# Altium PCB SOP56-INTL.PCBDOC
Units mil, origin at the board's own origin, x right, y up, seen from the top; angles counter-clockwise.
Board outline 1247.64 x 3931.89 mil, 2 copper layers (Top Layer, Bottom Layer); 6 components, 340 nets, 107 pads, 37 vias.
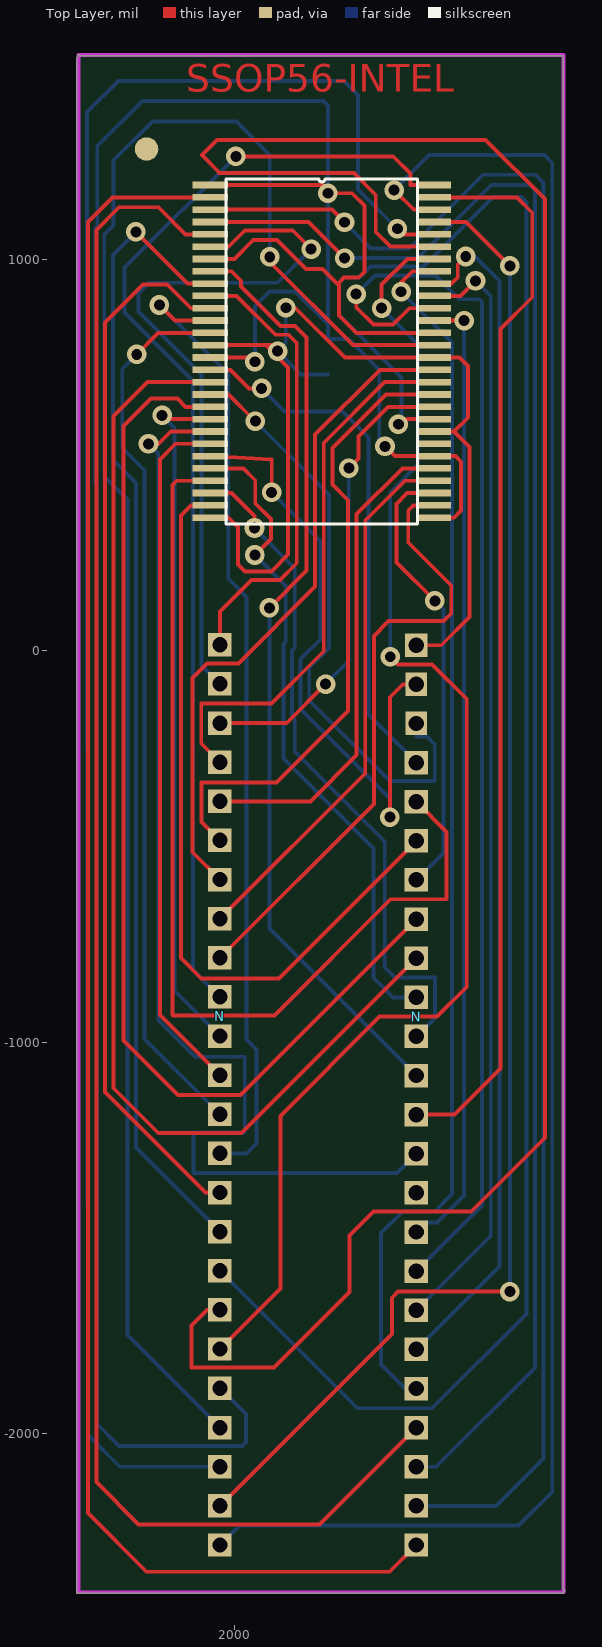
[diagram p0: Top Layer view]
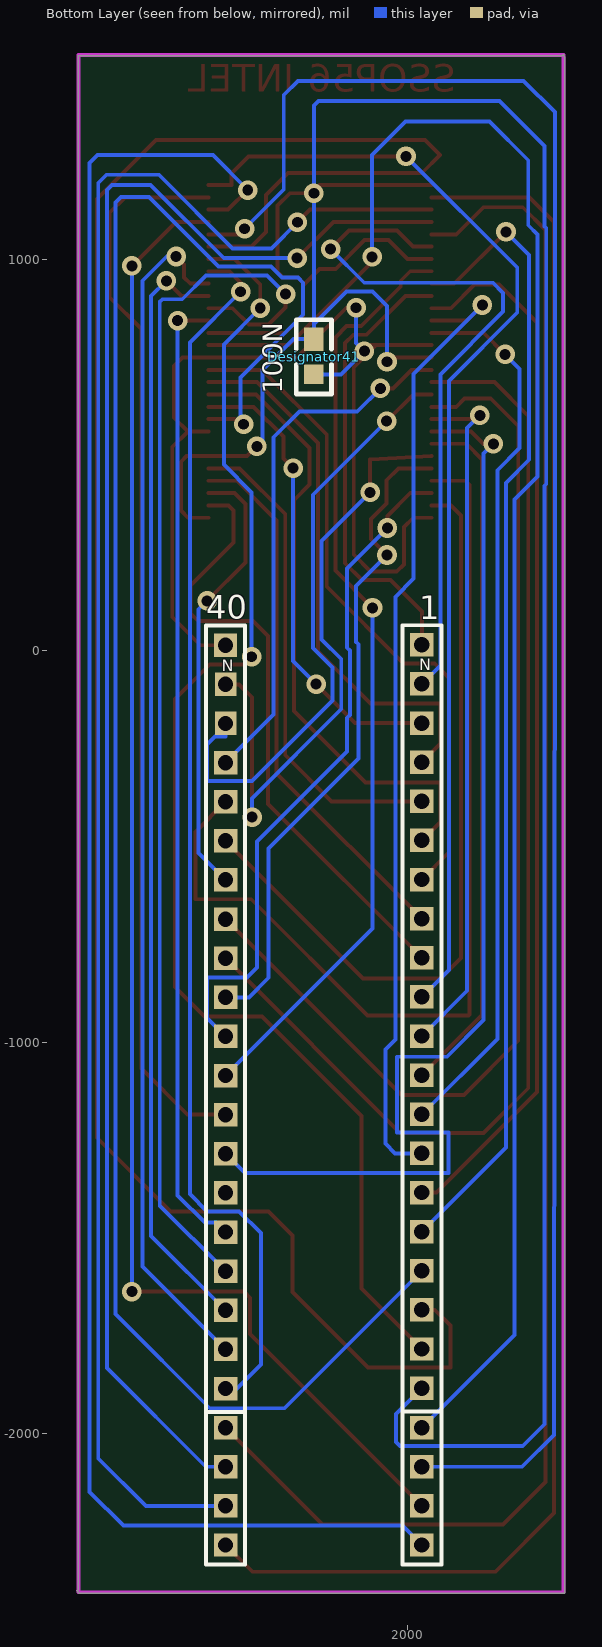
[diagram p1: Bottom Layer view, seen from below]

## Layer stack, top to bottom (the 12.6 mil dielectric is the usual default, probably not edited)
Top Layer: signal copper 1.4
Dielectric: dielectric 12.6, FR-4, Dk 4.8
Bottom Layer: signal copper 1.4

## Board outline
1599.21,1523.62 1601.18,1521.65 2840.94,1521.65 2840.94,-2398.43 2844.88,-2402.36 2838.98,-2408.27 1597.24,-2408.27 1597.24,1517.72 1603.15,1523.62

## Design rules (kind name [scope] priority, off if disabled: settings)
Clearance [All] p1: gap=12
ComponentClearance [All] p1 off: gap=10 collisioncheckmode=3 verticalgap=10 showdistances=FALSE
FabricationTestPointUsage TestPointUsage [All] p1: valid=0 allowmultiple=FALSE
FabricationTestpoint Testpoint [All] p1: side=3 testpointundercomponent=TRUE minsize=40 maxsize=100 preferedsize=60 minholesize=0 maxholesize=40 preferedholesize=32 testpointgrid=1 allowsidetop=TRUE allowsidebottom=TRUE usegrid=TRUE gridtolerance=0.01
HoleSize [All] p1: absolutevalues=TRUE maxlimit=1000 minlimit=1 maxpercent=80.000 minpercent=20.000
PolygonConnect [All] p1: connectstyle=Relief reliefconductorwidth=10 reliefentries=4 polygonreliefangle="90 Angle"
RoutingVias [All] p1: holewidth=28 width=50 viastyle="Through Hole" minholewidth=28 minwidth=50 maxholewidth=28 maxwidth=50
ShortCircuit [All] p1 off: allowed=FALSE
SilkscreenOverComponentPads [All] p1: minsilkscreentomaskgap=10
SolderMaskExpansion [All] p1: expansion=4
Width [All] p1: maxlimit=1000 minlimit=10 preferedwidth=10
22 further rules are at their usual default settings.

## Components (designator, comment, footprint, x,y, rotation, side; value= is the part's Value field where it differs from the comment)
Designator41 "100N" 0805 2239,797 r270 bottom
N "40" SIP20A#1 2464.92,14.69 r270 top
N "1" SIP20A#2 1962.92,15.68 r270 top
? "Comment" sip4#1 2464.92,-1985.32 r270 bottom
? "Comment" sip4#2 1962.92,-1985.32 r270 bottom
? "Comment" SOP56 1938,1191 r0 top

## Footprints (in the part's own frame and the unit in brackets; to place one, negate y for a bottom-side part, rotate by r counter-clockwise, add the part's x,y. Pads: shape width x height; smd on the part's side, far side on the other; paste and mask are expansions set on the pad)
0805 [mil]
  rect 60x50 smd: 1(0,0)
  rect 50x50 smd: 2(90,0)
  silkscreen extent -50,-45 140,45
sip4#1 [mil]
  rect 60x60 hole 39.37 mask+4: 25(300,0) 26(200,0) 27(100,0) 28(0,0)
  silkscreen extent -50,-50 350,50
sip4#2 [mil]
  rect 60x60 hole 39.37 mask+4: 21(0,0) 22(100,0) 23(200,0) 24(300,0)
  silkscreen extent -50,-50 350,50
SIP20A#1 [mil]
  rect 60x60 hole 39.37: 29(1900,0) 30(1800,0) 31(1700,0) 32(1600,0) 33(1500,0) 34(1400,0) 35(1300,0) 36(1200,0) 37(1100,0) 38(1000,0) 39(900,0) 40(800,0) 41(700,0) 42(600,0) 43(500,0) 44(400,0) 45(300,0)
  rect 60x55 hole 39.37: 46(200,0) 47(100,0)
  rect 60x58 hole 39.37: 48(0,0)
SIP20A#2 [mil]
  rect 60x60 hole 39.37: 1(0,0) 2(100,0) 3(200,0) 4(300,0) 5(400,0) 6(500,0) 7(600,0) 8(700,0) 9(800,0) 10(900,0) 11(1000,0) 12(1100,0) 13(1200,0) 14(1300,0) 15(1400,0) 16(1500,0) 17(1600,0) 18(1700,0) 19(1800,0) 20(1900,0)
SOP56 [mil]
  rect 90x17 smd: 1(0,0) 2(0,-31.5) 3(0,-62.99) 4(0,-94.49) 5(0,-125.98) 6(0,-157.48) 7(0,-188.98) 8(0,-220.47) 9(0,-251.97) 10(0,-283.46) 11(0,-314.96) 12(0,-346.46) 13(0,-377.95) 14(0,-409.45) 15(0,-440.95) 16(0,-472.44) 17(0,-503.94) 18(0,-535.43) 19(0,-566.93) 20(0,-598.43) 21(0,-629.92) 22(0,-661.42) 23(0,-692.91) 24(0,-724.41) 25(0,-755.91) 26(0,-787.4) 27(0,-818.9) 28(0,-850.39) 29(570.87,-850.39) 30(570.87,-818.9) 31(570.87,-787.4) 32(570.87,-755.91) 33(570.87,-724.41) 34(570.87,-692.91) 35(570.87,-661.42) 36(570.87,-629.92) 37(570.87,-598.43) 38(570.87,-566.93) 39(570.87,-535.43) 40(570.87,-503.94) 41(570.87,-472.44) 42(570.87,-440.95) 43(570.87,-409.45) 44(570.87,-377.95) 45(570.87,-346.46) 46(570.87,-314.96) 47(570.87,-283.46) 48(570.87,-251.97) 49(570.87,-220.47) 50(570.87,-188.98) 51(570.87,-157.48) 52(570.87,-125.98) 53(570.87,-94.49) 54(570.87,-62.99) 55(570.87,-31.5) 56(570.87,0)
  silkscreen extent 41,-866 530,16

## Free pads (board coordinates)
  round 60 smd: 0(1775.2,1283.07)

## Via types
v1: diameter 50, hole 28, Top Layer to Bottom Layer, 37 vias

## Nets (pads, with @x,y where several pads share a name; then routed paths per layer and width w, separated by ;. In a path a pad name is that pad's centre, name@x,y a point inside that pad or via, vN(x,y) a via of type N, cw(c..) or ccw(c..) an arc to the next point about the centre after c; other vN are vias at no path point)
a0: ?.37 N.17 | length 4962.1
  Top Layer w10: v1@2427.21,578.24 2441.54,592.57 ?.37
  Bottom Layer w10: N.17 2314.37,-1935.76 2505.21,-1935.76 2746.21,-1694.76 2746.21,1146.24 2732.21,1160.24 2660.9,1160.24 2482.9,982.24 2348.21,982.24 2320.21,954.24 2280.21,954.24 2267.21,941.24 2267.21,859.43 2427.21,699.43 v1@2427.21,578.24
  other v1: 2418.9,579.53
a1: ?.51 N.18 | length 5529.3
  Top Layer w10: 1959.84,1221.24 2305.21,1221.24 2361.21,1165.24 2361.21,1071.24 2398.93,1033.52 ?.51 ; 1962.2,1222.44 1916.73,1267.91 1955.06,1306.24 2642.21,1306.24 2793.7,1154.75 2793.7,-1244.27 2605.21,-1432.76 2355.21,-1432.76 2294.21,-1493.76 2294.21,-1638.76 2101.21,-1831.76 1890.16,-1831.76 1890.16,-1724.37 1930.21,-1684.31 N.18
a2: ?.50 N.19 | length 3427.7
  Top Layer w10: N.19 2117.21,-1630.03 2117.21,-1188.76 2371.21,-934.76 2518.21,-934.76 2593.7,-859.27 2593.7,-123.25 2505.21,-34.76 2418.21,-34.76 v1(2398.21,-14.76) ; v1(2376.21,876.24) 2376.21,936.24 2441.99,1002.02 ?.50
  Bottom Layer w10: v1(2376.21,876.24) 2469.21,783.24 2469.21,476.24 2398.21,405.24 v1(2398.21,-14.76)
a3: ?.49 N.29 | length 3152.8
  Top Layer w10: v1(2426.21,918.24) 2426.21,941.53 2455.21,970.53 ?.49
  Bottom Layer w10: v1(2426.21,918.24) 2556.21,788.24 2556.21,-1388.03 2511.92,-1432.31 2430.21,-1432.31 2374.8,-1487.72 2374.8,-1824.41 2435.71,-1885.31 N.29
a4: ?.48 N.30 | length 3061.6
  Top Layer w10: ?.48 2555.21,939.03 2570.87,954.69 2570.87,987.9 v1(2591.21,1008.24)
  Bottom Layer w10: N.30 2677.21,-1573.03 2677.21,946.24 2615.21,1008.24 v1(2591.21,1008.24)
a5: ?.47 N.31 | length 2849.9
  Top Layer w10: ?.47 2577.5,907.54 v1(2616.21,946.24)
  Bottom Layer w10: N.31 2655.21,-1495.03 2655.21,907.24 v1(2616.21,946.24)
a6: ?.46 N.32 | length 3184.5
  Top Layer w10: v1(2311.21,912.24) 2311.21,878.24 2355.21,834.24 2405.21,834.24 2447.01,876.04 ?.46
  Bottom Layer w10: v1(2311.21,912.24) 2359.21,960.24 2514.37,960.24 2575.68,898.93 2626.52,898.93 2633.21,892.24 2633.21,-1417.03 N.32
a7: ?.45 N.33 | length 2475.5
  Top Layer w10: ?.45 v1(2587.21,844.54)
  Bottom Layer w10: N.33 2489.33,-1460.91 2517.71,-1460.91 2587.21,-1391.41 v1(2587.21,844.54)
a8: ?.21@1962.92,-1985.31 ?.43 | length 4627.7
  Top Layer w10: v1(2090.21,1007.24) 2090.21,994.55 2303.21,781.55 ?.43
  Bottom Layer w10: ?.21@1962.92,-1985.31 1726.21,-1748.6 1726.21,387.24 1667.18,446.27 1667.18,1064.14 1691.21,1088.17 1691.21,1254.24 1790.21,1353.24 2005.01,1353.24 2090.21,1268.04 v1(2090.21,1007.24)
a9: ?.22@1962.92,-2085.31 ?.52 | length 4975.5
  Top Layer w10: v1(2416.21,1079.24) 2430.44,1065.02 ?.52
  Bottom Layer w10: ?.22@1962.92,-2085.31 1706.77,-2085.31 1625.21,-2003.76 1623.18,329.27 1623.18,1377.22 1703.21,1457.24 2280.21,1457.24 2316.21,1421.24 2316.21,1179.24 v1(2416.21,1079.24)
a10: ?.23@1962.92,-2185.31 ?.53 | length 3886.3
  Top Layer w10: ?.23@1962.92,-2185.31 2402.21,-1746.03 2402.21,-1653.26 2417.71,-1637.76 v1(2704.21,-1637.76) ; ?.53 2591.94,1096.51 v1(2704.21,984.24)
  Bottom Layer w10: v1(2704.21,-1637.76) v1(2704.21,984.24)
a11: ?.24@1962.92,-2285.31 ?.54 | length 4873.3
  Top Layer w10: v1(2408.21,1178.01) 2458.21,1128.01 ?.54
  Bottom Layer w10: ?.24@1962.92,-2285.31 2012.48,-2235.76 2726.21,-2235.76 2812.21,-2149.76 2812.21,1247.74 2792.71,1267.24 2497.45,1267.24 v1(2408.21,1178.01)
a12: ?.2 ?.25@2464.92,-2285.31 | length 4569.2
  Top Layer w10: ?.2 1688.47,1159.5 1625.21,1096.24 1625.21,-2203.76 1775.21,-2353.76 2396.48,-2353.76 ?.25@2464.92,-2285.31
a13: ?.3 ?.26@2464.92,-2185.31 | length 4615.4
  Top Layer w10: ?.3 2249.09,1128.01 v1(2281.21,1095.89)
  Bottom Layer w10: v1(2281.21,1095.89) 2347.97,1029.13 2446.85,1029.13 2634.96,1217.24 2769.21,1217.24 2790.21,1196.24 2790.21,-2063.76 2668.65,-2185.31 ?.26@2464.92,-2185.31
a14: ?.4 ?.27@2464.92,-2085.31 | length 4370.1
  Top Layer w10: ?.4 2189.44,1096.51 v1(2281.71,1004.24)
  Bottom Layer w10: v1(2281.71,1004.24) 2469.44,1004.24 2656.44,1191.24 2755.21,1191.24 2768.21,1178.24 2768.21,-1832.58 2515.47,-2085.31 ?.27@2464.92,-2085.31
a15: ?.5 ?.28@2464.92,-1985.31 | length 4509.4
  Top Layer w10: ?.5 1875.21,1065.02 1805.98,1134.24 1705.21,1134.24 1647.21,1076.24 1647.21,-2124.76 1755.21,-2232.76 2217.48,-2232.76 ?.28@2464.92,-1985.31
a16: ?.13 N.13 | length 2271.8
  Top Layer w10: v1(1750.21,758.24) 1805.01,813.05 ?.13
  Bottom Layer w10: v1(1750.21,758.24) 1713.21,721.24 1713.21,518.95 1770.21,461.95 1770.21,-991.6 N.13
a17: ?.12 N.14 | length 2496.4
  Top Layer w10: v1(1808.21,884.24) 1847.91,844.54 ?.12
  Bottom Layer w10: v1(1808.21,884.24) 1984.21,708.24 1984.21,184.69 2030.71,138.19 2030.71,-993.31 2056.3,-1018.9 2056.3,-1259.45 2031.43,-1284.31 N.14
a18: ?.11 N.15 | length 2700.9
  Top Layer w10: ?.11 1888.41,876.04 1828.21,936.24 1766.21,936.24 1669.21,839.24 1669.21,-1127.76 1925.77,-1384.31 N.15
a19: ?.10 N.1 | length 1166.4
  Top Layer w10: ?.10 2005.21,907.54 2104.5,808.24 2137.97,808.24 2159.21,787.01 2159.21,224.24 2116.21,181.24 2043.42,181.24 1962.92,100.75 N.1
a20: ?.9 N.16 | length 2937.9
  Top Layer w10: v1(1748.1,1071.14) 1880.21,939.03 ?.9
  Bottom Layer w10: v1(1748.1,1071.14) 1689.18,1012.22 1689.18,488.8 1748.21,429.77 1748.21,-1269.6 N.16
a21: ?.8 N.37 | length 2406.7
  Top Layer w10: ?.8 1992.84,970.53 2017.12,946.24 2017.12,931.24 2118.11,830.24 2155.21,830.24 2184.21,801.24 2184.21,205.24 v1(2089.21,110.24)
  Bottom Layer w10: v1(2089.21,110.24) 2089.21,-709.6 N.37
a22: ?.6 N.2 | length 1867.5
  Top Layer w10: ?.6 1985.49,1033.52 2026.21,1074.24 2149.06,1074.24 v1(2196.21,1027.1)
  Bottom Layer w10: N.2 1915.92,-37.31 1915.92,706.53 1755.21,867.24 1755.21,915.24 1781.21,941.24 2110.36,941.24 v1(2196.21,1027.1)
a23: N.34
a24: ?.23@1938,498.09 N.47 | length 1625.8
  Top Layer w10: ?.23@1938,498.09 2095.21,489.24 v1(2095.21,405.24) ; v1(2397.21,-424.76) 2397.21,-118.31 2430.21,-85.31 N.47
  Bottom Layer w10: v1(2095.21,405.24) 2219.21,281.24 2219.21,29.24 2169.21,-20.76 2169.21,-148.76 2397.21,-376.76 v1(2397.21,-424.76)
a25: 
a26: 
b1: 
b2: 
b3: 
b4: 
b5: 
b6: 
b7: 
b8: 
b9: 
b10: 
b11: 
b12: 
b13: 
b14: 
b16: 
b17: 
b18: 
b19: 
b20: 
b21: 
b22: 
byte: 
ce: 
CE1: 
CS: 
D0: ?.38 N.3 | length 1202.4
  Top Layer w10: N.3 2133.65,-184.31 v1(2233.21,-84.76) ; v1(2292.21,467.24) 2317.21,492.24 2317.21,548.31 2392.97,624.07 ?.38
  Bottom Layer w10: v1(2233.21,-84.76) 2292.21,-25.76 v1(2292.21,467.24)
D1: ?.40 N.4 | length 1415
  Top Layer w10: N.4 1915.21,-236.6 1915.21,-134.76 2094.21,-134.76 2228.21,-0.76 2228.21,531.24 2384.03,687.06 ?.40
D2: ?.33 N.5 | length 1259.2
  Top Layer w10: N.5 2194.21,-384.31 2312.21,-266.31 2312.21,349.59 2429.21,466.59 ?.33
D3: ?.31 N.42 | length 1146
  Top Layer w10: ?.31 2441.56,403.6 2413.91,375.94 2413.91,226.55 v1(2512.21,128.24)
  Bottom Layer w10: N.42 2533.92,-516.31 2533.92,106.53 v1(2512.21,128.24)
D4: ?.27@1938,372.1 N.43 | length 1985.3
  Top Layer w10: ?.27@1938,372.1 1889.07,372.1 1863.21,346.24 1863.21,-784.76 1915.21,-836.76 2113.48,-836.76 N.43
D5: ?.25@1938,435.09 N.44 | length 2561.5
  Top Layer w10: ?.25@1938,435.09 1852.06,435.09 1841.21,424.24 1841.21,-929.76 1843.21,-931.76 2102.21,-931.76 2399.21,-634.76 2542.13,-634.76 2542.13,-462.52 N.44
D6: ?.16 N.45 | length 1358
  Top Layer w10: ?.16 1989.72,718.56 2037.04,671.24 v1(2069.21,671.24)
  Bottom Layer w10: v1(2069.21,671.24) 2128.21,612.24 2276.21,612.24 2342.21,546.24 2342.21,-162.6 N.45
D7: ?.18 N.46 | length 1544.9
  Top Layer w10: ?.18 1984.89,655.57 v1(2053.21,587.24)
  Bottom Layer w10: v1(2053.21,587.24) 2241.21,399.24 2241.21,7.24 2191.21,-42.76 2191.21,-126.76 2397.21,-332.76 2511.92,-332.76 2511.92,-238.76 2491.92,-218.76 2464.92,-218.76 N.46
D8: ?.39 N.6 | length 1621.4
  Top Layer w10: N.6 1915.92,-437.31 1915.92,-336.76 2107.42,-336.76 2290.21,-153.96 2290.21,385.24 2250.21,425.24 2250.21,518.32 2387.46,655.57 ?.39
D9: ?.41 N.7 | length 1714.1
  Top Layer w10: N.7 1893.21,-514.6 1893.21,-68.76 1930.21,-31.76 2010.21,-31.76 2206.21,164.24 2206.21,553.24 2371.52,718.56 ?.41
D10: ?.32 N.8 | length 1388.2
  Top Layer w10: N.8 2334.21,-313.03 2334.21,333.24 2436.06,435.09 ?.32
D11: ?.30 N.9 | length 1586
  Top Layer w10: N.9 2356.21,-391.03 2356.21,38.69 2394.21,76.69 2534.65,76.69 2554.21,96.24 2554.21,167.24 2444.21,277.24 2444.21,358.74 2457.57,372.1 ?.30
D12: ?.26@1938,403.6 N.38 | length 1743.9
  Top Layer w10: ?.26@1938,403.6 1992.71,403.6 2051.21,345.1 v1(2051.21,314.24)
  Bottom Layer w10: v1(2051.21,314.24) 2154.21,211.24 2154.21,8.24 2147.21,1.24 2147.21,-163.76 2154.21,-170.76 2154.21,-257.06 2384.25,-487.1 2384.25,-808.66 2410.35,-834.76 2512.21,-834.76 2512.21,-938.03 N.38
D13: ?.24@1938,466.59 N.39 | length 1693.8
  Top Layer w10: ?.24@1938,466.59 2022.86,466.59 2053.21,436.24 2053.21,377.06 2093.21,337.06 2093.21,286.24 v1(2052.21,245.24)
  Bottom Layer w10: v1(2052.21,245.24) 2131.21,166.24 2131.21,23.24 2125.21,17.24 2125.21,-274.72 2355.21,-504.72 2355.21,-835.31 2405.21,-885.31 N.39
D14: ?.17 N.40 | length 3007
  Top Layer w10: ?.17 1777.33,687.06 1691.21,600.94 1691.21,-1117.76 1805.21,-1231.76 2018.48,-1231.76 N.40
D15: ?.19 N.41 | length 2821.9
  Top Layer w10: ?.19 1875.21,624.07 1854.27,645.01 1786.97,645.01 1716.64,574.68 1716.64,-996.19 1855.21,-1134.76 2015.48,-1134.76 N.41
D16: 
D17: 
D18: 
D19: 
D20: 
D21: 
D22: 
D23: 
D24: 
D25: 
D26: 
D27: 
D28: 
D29: 
D30: 
D31: 
D32: 
D33: 
D34: 
D35: 
D36: 
D37: 
D38: 
D39: 
D40: 
D41: 
D42: 
D43: 
D44: 
D45: 
D46: 
D47: 
D48: 
D49: 
D50: 
D51: 
D52: 
D53: 
D54: 
D55: 
D56: 
GND: ?.1 ?.7 ?.15 ?.29 ?.34 ?.44 Designator41.1 N.20 | length 7882.2
  Top Layer w10: ?.15 2041.4,750.05 v1(2052.21,739.24) ; ?.7 1999.77,1002.02 2047.99,1050.24 2109.21,1050.24 2183.21,976.24 2225.21,976.24 2267.21,934.24 ; ?.1 2225.14,1191 v1@2242.52,1173.62 ; v1(2239,1170.01) 2300.38,1170.01 2332.18,1138.21 2332.18,968.71 2317.71,954.24 2280.21,954.24 2267.21,941.24 2267.21,934.24 ; v1(2384.87,523.09) 2409.87,498.09 ?.34 2564.87,498.09 2579.21,483.74 2579.21,358.74 2561.07,340.61 ?.29 ; ?.44 2453.21,813.05 2452.41,812.24 2312.21,812.24 2267.21,857.24 ; 2267.21,857.24 2267.21,934.24 ; 2267.21,857.24 2267.21,934.24
  Bottom Layer w10: N.20 2029.21,-1950.6 2029.21,-2022.36 2018.82,-2032.76 1705.21,-2032.76 1649.21,-1976.76 1649.21,422.24 1645.18,426.27 1645.18,1081.22 1649.21,1085.24 1649.21,1290.94 1764.51,1406.24 2227.21,1406.24 2239,1394.45 v1(2239,1170.01) 2239,1107.45 2239,835.45 ; v1(2052.21,739.24) 2052.21,882.24 2089.21,919.24 2155.21,919.24 2239,835.45 ; v1(2384.87,523.09) 2370.08,537.87 2370.08,718.38 2291.45,797 Designator41.1 ; Designator41.1 2239,835.45 ; Designator41.1 2239,835.45
gnd1: 
gnd2: 
gnd3: 
h0: 
h1: 
h2: 
h3: 
h4: 
h5: 
h6: 
h7: 
h8: 
h9: 
h10: 
h11: 
h12: 
h13: 
h14: 
h15: 
h16: 
h17: 
h18: 
h19: 
HV: 
i0: 
i1: 
i2: 
i3: 
i4: 
i5: 
i6: 
i7: 
LE: 
m1: 
m2: 
m3: 
m4: 
m5: 
m6: 
m7: 
m8: 
m9: 
m10: 
m11: 
m12: 
m13: 
m14: 
m15: 
m16: 
m17: 
m18: 
m19: 
m20: 
m21: 
m22: 
m23: 
m24: 
m25: 
m26: 
m27: 
m28: 
m29: 
m30: 
m31: 
m32: 
m33: 
m34: 
m35: 
m36: 
m37: 
m38: 
m39: 
m40: 
MCLR: 
o0: 
o1: 
o2: 
o3: 
o4: 
o5: 
o6: 
o7: 
o8: 
o9: 
o10: 
o11: 
o12: 
o13: 
o14: 
o15: 
o16: 
oe: ?.21@1938,561.08 N.35 | length 2932.9
  Top Layer w10: v1(1780.21,529.24) 1805.21,529.24 1837.04,561.08 ?.21@1938,561.08
  Bottom Layer w10: v1(1780.21,529.24) 1805.21,504.24 1805.21,-943.78 1898.74,-1037.31 2026.38,-1037.31 2026.38,-1231.31 1895.28,-1231.31 1895.28,-1334.76 2415.48,-1334.76 N.35
P1: 
P2: 
P3: 
P4: 
P5: 
P6: 
P7: 
P8: 
P9: 
P9IN: 
P10: 
P11: 
P11IN: 
P12: 
P13: 
P13IN: 
P14: 
P15: 
P16: 
P17: 
P18: 
P19: 
P20: 
P21: 
P22: 
P23: 
P24: 
P25: 
P26: 
P27: 
P28: 
P29: 
P30: 
P31: 
P32: 
P33: 
P34: 
P35: 
P36: 
P37: 
P38: 
P39: 
P40: 
P41: 
P42: 
P43: 
P44: 
P45: 
P46: 
P47: 
P48: 
q0: 
q1: 
q2: 
q3: 
q4: 
q5: 
q6: 
q7: 
RA0: 
RA1: 
RA2: 
RDY: ?.20 N.11 | length 1775
  Top Layer w10: v1(1814.88,602.24) 1824.55,592.57 ?.20
  Bottom Layer w10: v1(1814.88,602.24) 1847.21,569.91 1847.21,-868.6 N.11
RES1: 
RES2: 
RST: ?.55 N.36 | length 2754.1
  Top Layer w10: N.36 2562.72,-1185.31 2680.21,-1067.82 2680.21,823.2 2761.21,904.2 2761.21,1120.19 2721.9,1159.5 ?.55
S1: 
S2: 
S3: 
S4: 
S5: 
S6: 
S7: 
S8: 
S9: 
S10: 
S11: 
S12: 
S13: 
S14: 
S15: 
S16: 
S17: 
S18: 
S19: 
S21: 
S22: 
S23: 
S24: 
S25: 
S26: 
S27: 
S28: 
S29: 
S30: 
S31: 
S32: 
S33: 
S34: 
S35: 
S36: 
S37: 
S38: 
S39: 
SCK: 
SDI: 
SDO: 
TCK: 
tdI: 
tdo: 
TMS: 
VCC: ?.14 ?.28@1938,340.61 ?.36 ?.42 Designator41.2 N.48 | length 2900.4
  Top Layer w10: ?.28@1938,340.61 1985.21,340.61 2009.21,316.61 2009.21,221.24 2027.21,203.24 2094.21,203.24 2137.21,246.24 2137.21,724.55 2102.86,758.9 2080.21,781.55 ; v1(2110.21,766.24) 2094.9,781.55 2080.21,781.55 ; v1(2131.21,877.24) 2155.21,877.24 2282.4,750.05 ?.42 2574.75,750.05 2596.46,728.35 2596.46,596.16 2561.38,561.08 ; N.48 2528.65,14.69 2601.21,87.24 2601.21,521.24 2561.38,561.08 ; ?.36 2561.38,561.08 ; 2080.21,781.55 ?.14 2080.21,781.55
  Bottom Layer w10: v1(2131.21,877.24) 2131.21,787.24 v1(2110.21,766.24) 2169.45,707 Designator41.2
vcc1: 
vcc2: 
vcc3: 
vcc3.3: 
vcc3sel: 
vcc5sel: 
vccen: 
vccen8: 
vccen12: 
vccen37: 
vccen38: 
vccsel: 
VPEN: ?.56 N.10 | length 2919.9
  Top Layer w10: v1(2003.67,1264.24) 2405.97,1264.24 2450.21,1220.01 2450.21,1191 ?.56
  Bottom Layer w10: N.10 1893.92,-815.31 1893.92,690.53 1719.21,865.24 1719.21,979.79 v1(2003.67,1264.24)
vpp: 
vpp1: 
vpp31: 
vppen9: 
vppen11: 
vppen13: 
VPPH9: 
VPPH11: 
VPPH13: 
VPPL9: 
VPPL11: 
VPPL13: 
WR: ?.22@1938,529.58 N.12 | length 1782.9
  Top Layer w10: ?.22@1938,529.58 1849.31,529.58 1809.21,489.48 1809.21,-930.6 N.12
pads on no net: ?.35

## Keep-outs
Keep-Out Layer:
  lines w10: 1601.18,-2406.02 2840.94,-2406.02 2840.94,1523.62 1601.18,1523.62 1601.18,-2406.02

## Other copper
Top Layer:
  text "SSOP56-INTEL" at 1876.77,1429.13 h70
